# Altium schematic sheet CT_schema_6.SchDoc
size 287 x 160 mm
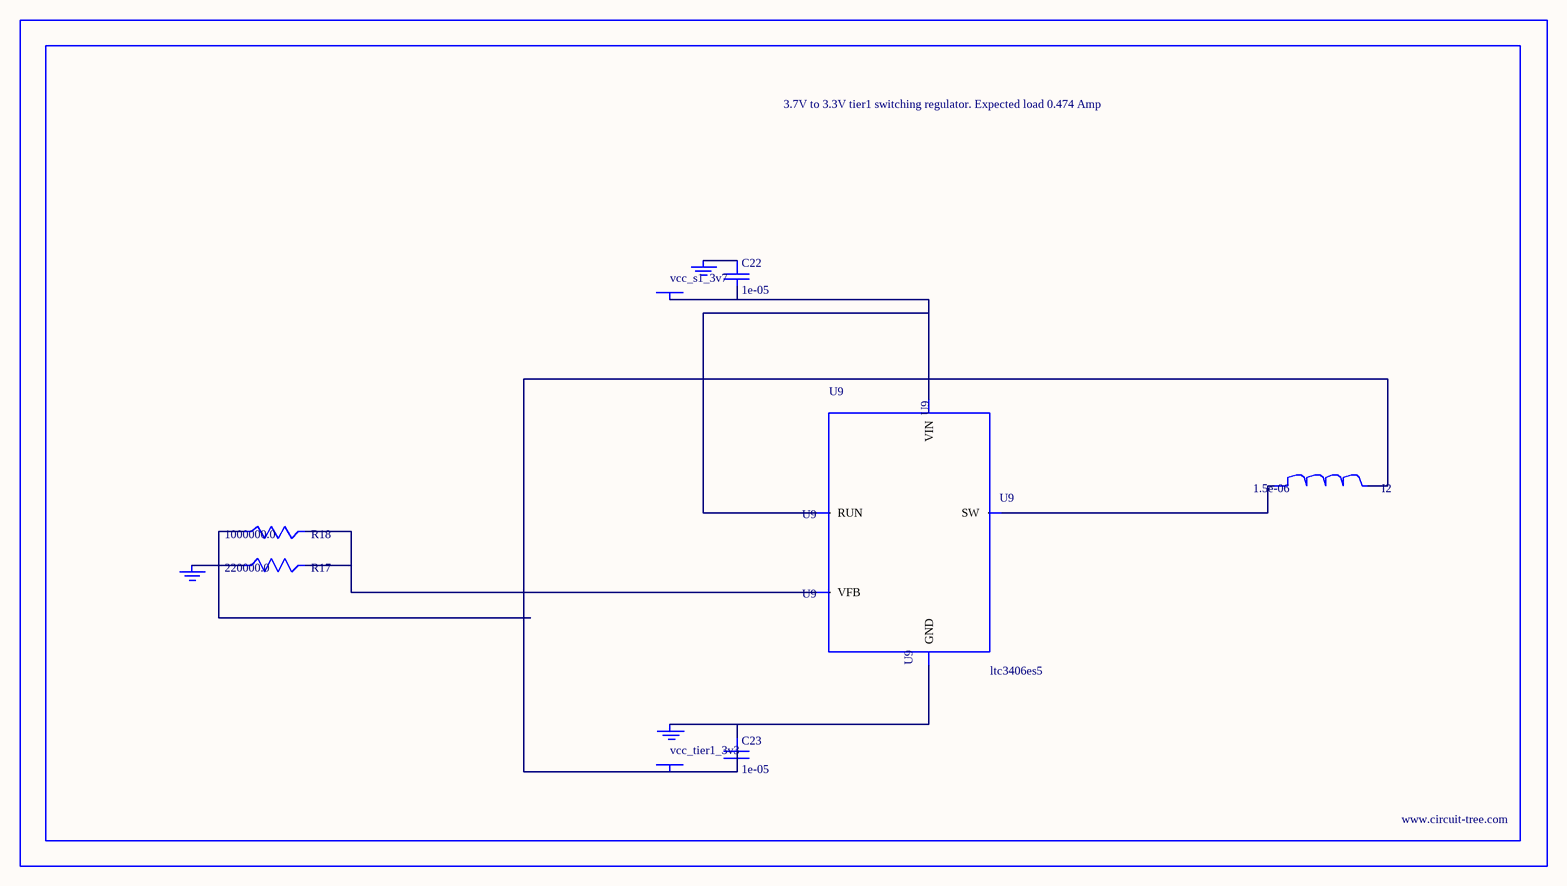
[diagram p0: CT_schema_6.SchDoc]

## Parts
BORDER5  (no value)
C22  1e-05  [C0805]
C23  1e-05  [C0805]
GND_INSTANCE_5_0  (no value)
GND_INSTANCE_5_1  (no value)
GND_INSTANCE_5_2  (no value)
I2  1.5e-06  [L0806]
POWER_INSTANCE_5_0  vcc_tier1_3v3
POWER_INSTANCE_5_1  vcc_s1_3v7
R17  220000.0  [R0603]
R18  1000000.0  [R0603]
U9  ltc3406es5  [TSOT-23-5]

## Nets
NetC22_1: C22.1 GND_INSTANCE_5_1.0(GND)
NetC22_2: C22.2 POWER_INSTANCE_5_1.0(PWR) U9.1(RUN) U9.4(VIN)
NetC23_1: C23.1 GND_INSTANCE_5_0.0(GND) U9.2(GND)
NetC23_2: C23.2 I2.2 POWER_INSTANCE_5_0.0(PWR) R18.1
NetGND_INSTANCE_5_2_0: GND_INSTANCE_5_2.0(GND) R17.1
NetI2_1: I2.1 U9.3(SW)
NetR17_2: R17.2 R18.2 U9.5(VFB)

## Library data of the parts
BORDER5 = BORDER_PAGE5
C22 C23 = C0805C106K8RACTU
GND_INSTANCE_5_0-GND_INSTANCE_5_2 = GND
I2 = L0806C1R5MDWIT
POWER_INSTANCE_5_0 POWER_INSTANCE_5_1 = PWR
R17 = RC0603JR-07220KL
R18 = RC0603JR-071ML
